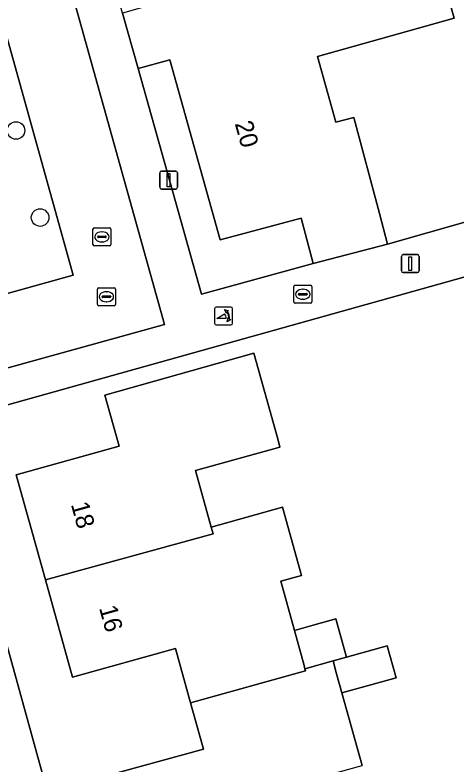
# Model space of a CAD drawing. Extents: x 159626 to 160723, y 388173 to 389416.
# Drawn here: x 159874.74 to 159899.35, y 388342.68 to 388384.45 of the extents above; entities that cross this region are included whole.
import ezdxf

# ---------------------------------------------------------------- set-up
doc = ezdxf.new("R2010")
doc.units = 0
for name, color, linetype in [('IMGEO_Boom', 7, 'Continuous'), ('IMGEO_Erf', 7, 'Continuous'), ('IMGEO_Kolk', 7, 'Continuous'), ('IMGEO_Lichtmast', 7, 'Continuous'), ('IMGEO_Muur', 7, 'Continuous'), ('IMGEO_Pand', 7, 'Continuous'), ('IMGEO_Pand_nummerreeks', 7, 'Continuous'), ('IMGEO_Poller', 7, 'Continuous'), ('IMGEO_Rijbaan_lokaal_open', 7, 'Continuous'), ('IMGEO_Rioolput', 7, 'Continuous'), ('IMGEO_Voetpad_open', 7, 'Continuous')]:
    doc.layers.add(name, color=color, linetype=linetype)

msp = doc.modelspace()

# ---------------------------------------------------------------- linework, layer by layer
at = {"layer": 'IMGEO_Boom'}
for centre in [(159874.792, 388378.012), (159876.137, 388373.166)]:
    msp.add_circle(centre, 0.489, dxfattribs=at)
at = {"layer": 'IMGEO_Erf'}
for points in [[(159897.841, 388389.08), (159899.191, 388384.265), (159891.585, 388382.133), (159892.611, 388378.475), (159893.612, 388378.74), (159895.026, 388373.388), (159895.473, 388371.693), (159906.895, 388374.924), (159927.612, 388380.783), (159924.091, 388393.285)], [(159928.443, 388377.878), (159922.592, 388376.25), (159923.589, 388372.697), (159917.967, 388371.119), (159916.97, 388374.672), (159872.396, 388362.2)], [(159879.487, 388341.978), (159885.23, 388343.569), (159884.516, 388346.144), (159883.678, 388349.167), (159877.935, 388347.575), (159876.429, 388352.983), (159874.798, 388358.84), (159880.533, 388360.43), (159879.743, 388363.284), (159888.04, 388365.621), (159889.386, 388360.769), (159889.493, 388360.383), (159884.791, 388359.08), (159885.664, 388355.932), (159889.63, 388357.031), (159890.683, 388353.233), (159889.532, 388352.914), (159890.293, 388350.17), (159891.347, 388350.462), (159892.607, 388350.811), (159893.195, 388348.685), (159895.465, 388349.314), (159895.961, 388347.528), (159892.943, 388346.691), (159894.061, 388342.653)], [(159871.278, 388360.217), (159878.48, 388334.175)]]:
    msp.add_lwpolyline(points, dxfattribs=at)
msp.add_lwpolyline([(159885.125, 388368.905), (159891.335, 388370.601), (159890.887, 388372.296), (159890.669, 388373.125), (159886.156, 388371.934), (159883.367, 388381.942), (159881.588, 388381.462)], close=True, dxfattribs=at)
at = {"layer": 'IMGEO_Kolk'}
for p, q in [((159879.08, 388371.665), (159879.08, 388372.517)), ((159879.155, 388372.591), (159880.007, 388372.591)), ((159880.081, 388372.517), (159880.081, 388371.665)), ((159879.339, 388372.085), (159879.339, 388372.097)), ((159879.777, 388372.048), (159879.379, 388372.048)), ((159879.382, 388372.134), (159879.78, 388372.134)), ((159879.568, 388372.371), (159879.593, 388372.371)), ((159879.823, 388372.097), (159879.823, 388372.085)), ((159879.591, 388371.811), (159879.566, 388371.811)), ((159880.007, 388371.591), (159879.155, 388371.591)), ((159890.264, 388368.468), (159890.264, 388369.32)), ((159890.339, 388369.394), (159891.191, 388369.394)), ((159890.752, 388369.174), (159890.777, 388369.174)), ((159891.265, 388369.32), (159891.265, 388368.468)), ((159890.523, 388368.888), (159890.523, 388368.9)), ((159890.961, 388368.851), (159890.563, 388368.851)), ((159890.566, 388368.937), (159890.964, 388368.937)), ((159891.007, 388368.9), (159891.007, 388368.888)), ((159891.191, 388368.394), (159890.339, 388368.394)), ((159890.775, 388368.614), (159890.75, 388368.614))]:
    msp.add_line(p, q, dxfattribs=at)
for points in [[(159879.08, 388371.665), (159879.08, 388372.517)], [(159879.155, 388372.591), (159880.007, 388372.591)], [(159880.081, 388372.517), (159880.081, 388371.665)], [(159880.007, 388371.591), (159879.155, 388371.591)], [(159890.264, 388368.468), (159890.264, 388369.32)], [(159890.339, 388369.394), (159891.191, 388369.394)], [(159891.265, 388369.32), (159891.265, 388368.468)], [(159891.191, 388368.394), (159890.339, 388368.394)]]:
    msp.add_lwpolyline(points, dxfattribs=at)
for centre, radius, start, end in [((159879.157, 388372.515), 0.0765, 91.552, 178.448), ((159879.157, 388372.515), 0.0765, 91.552, 178.448), ((159880.005, 388372.515), 0.0765, 1.552, 88.448), ((159880.005, 388372.515), 0.0765, 1.552, 88.448), ((159879.379, 388372.094), 0.0403, 85.8775, 175.7526), ((159879.376, 388372.084), 0.0366, 178.938, 274.7102), ((159879.78, 388372.091), 0.043, 264.8664, 352.4533), ((159879.784, 388372.096), 0.0386, 1.7309, 96.639), ((159879.157, 388371.667), 0.0765, 181.552, 268.448), ((159879.157, 388371.667), 0.0765, 181.552, 268.448), ((159880.005, 388371.667), 0.0765, 271.552, 358.448), ((159880.005, 388371.667), 0.0765, 271.552, 358.448), ((159890.341, 388369.318), 0.0765, 91.552, 178.448), ((159890.341, 388369.318), 0.0765, 91.552, 178.448), ((159891.189, 388369.318), 0.0765, 1.552, 88.448), ((159891.189, 388369.318), 0.0765, 1.552, 88.448), ((159890.563, 388368.897), 0.0403, 85.8775, 175.7526), ((159890.56, 388368.887), 0.0366, 178.938, 274.7102), ((159890.964, 388368.894), 0.043, 264.8664, 352.4533), ((159890.968, 388368.899), 0.0386, 1.7309, 96.639), ((159890.341, 388368.47), 0.0765, 181.552, 268.448), ((159890.341, 388368.47), 0.0765, 181.552, 268.448), ((159891.189, 388368.47), 0.0765, 271.552, 358.448), ((159891.189, 388368.47), 0.0765, 271.552, 358.448)]:
    msp.add_arc(centre, radius, start, end, dxfattribs=at)
for centre, major_axis, ratio, start_param, end_param in [((159879.567, 388372.091), (-0.387, 0.002), 0.722429, 4.712389, 7.853982), ((159879.592, 388372.091), (-0.39, 0.002), 0.717154, 1.570796, 4.712389), ((159890.751, 388368.894), (-0.387, 0.002), 0.722429, 4.712389, 7.853982), ((159890.776, 388368.894), (-0.39, 0.002), 0.717154, 1.570796, 4.712389)]:
    msp.add_ellipse(centre, major_axis=major_axis, ratio=ratio, start_param=start_param, end_param=end_param, dxfattribs=at)
at = {"layer": 'IMGEO_Lichtmast'}
for p, q in [((159882.795, 388374.852), (159882.795, 388375.652)), ((159882.795, 388375.652), (159882.795, 388374.852)), ((159882.895, 388375.752), (159883.685, 388375.752)), ((159883.685, 388375.752), (159882.895, 388375.752)), ((159883.785, 388375.652), (159883.785, 388374.852)), ((159883.785, 388374.852), (159883.785, 388375.652)), ((159883.685, 388374.752), (159882.895, 388374.752)), ((159882.895, 388374.752), (159883.685, 388374.752)), ((159896.252, 388370.201), (159896.252, 388371.001)), ((159896.252, 388371.001), (159896.252, 388370.201)), ((159896.352, 388371.101), (159897.142, 388371.101)), ((159897.142, 388371.101), (159896.352, 388371.101)), ((159897.242, 388371.001), (159897.242, 388370.201)), ((159897.242, 388370.201), (159897.242, 388371.001)), ((159897.142, 388370.101), (159896.352, 388370.101)), ((159896.352, 388370.101), (159897.142, 388370.101))]:
    msp.add_line(p, q, dxfattribs=at)
for points in [[(159883.215, 388375.627), (159883.365, 388375.627), (159883.365, 388374.877), (159883.215, 388374.877), (159883.215, 388375.627)], [(159896.672, 388370.976), (159896.822, 388370.976), (159896.822, 388370.226), (159896.672, 388370.226), (159896.672, 388370.976)]]:
    msp.add_lwpolyline(points, dxfattribs=at)
for centre, start, end in [((159882.895, 388375.652), 90, 180), ((159882.895, 388375.652), 90, 180), ((159883.685, 388375.652), 0, 90), ((159883.685, 388375.652), 360, 90), ((159882.895, 388374.852), 180, 270), ((159882.895, 388374.852), 180, 270), ((159883.685, 388374.852), 270, 0), ((159883.685, 388374.852), 270, 0), ((159896.352, 388371.001), 90, 180), ((159896.352, 388371.001), 90, 180), ((159897.142, 388371.001), 0, 90), ((159897.142, 388371.001), 360, 90), ((159896.352, 388370.201), 180, 270), ((159896.352, 388370.201), 180, 270), ((159897.142, 388370.201), 270, 0), ((159897.142, 388370.201), 270, 0)]:
    msp.add_arc(centre, 0.1, start, end, dxfattribs=at)
at = {"layer": 'IMGEO_Muur'}
msp.add_lwpolyline([(159895.473, 388371.693), (159906.895, 388374.924)], dxfattribs=at)
at = {"layer": 'IMGEO_Pand'}
for points in [[(159897.753, 388389.394), (159880.723, 388384.547), (159881.588, 388381.462), (159883.367, 388381.942), (159886.156, 388371.934), (159890.669, 388373.125), (159890.887, 388372.296), (159891.335, 388370.601), (159895.473, 388371.693), (159895.026, 388373.388), (159893.612, 388378.74), (159892.611, 388378.475), (159891.585, 388382.133), (159899.191, 388384.265), (159897.841, 388389.08)], [(159889.493, 388360.383), (159889.386, 388360.769), (159888.04, 388365.621), (159879.743, 388363.284), (159880.533, 388360.43), (159874.798, 388358.84), (159876.429, 388352.983), (159885.769, 388355.555), (159885.664, 388355.932), (159884.791, 388359.08)], [(159885.664, 388355.932), (159885.769, 388355.555), (159876.429, 388352.983), (159877.935, 388347.575), (159883.678, 388349.167), (159884.516, 388346.144), (159890.918, 388347.916), (159890.882, 388348.044), (159890.832, 388348.226), (159890.293, 388350.17), (159889.532, 388352.914), (159890.683, 388353.233), (159889.63, 388357.031)], [(159890.293, 388350.17), (159890.832, 388348.226), (159890.882, 388348.044), (159892.448, 388348.478), (159893.195, 388348.685), (159892.607, 388350.811), (159891.347, 388350.462)], [(159895.465, 388349.314), (159893.195, 388348.685), (159892.448, 388348.478), (159892.646, 388347.764), (159892.943, 388346.691), (159895.961, 388347.528)], [(159894.061, 388342.653), (159892.943, 388346.691), (159892.646, 388347.764), (159892.448, 388348.478), (159890.882, 388348.044), (159890.918, 388347.916), (159884.516, 388346.144), (159885.23, 388343.569), (159879.487, 388341.978), (159881.098, 388336.221), (159883.364, 388336.844), (159883.902, 388334.886), (159888.714, 388336.209), (159888.176, 388338.166), (159890.43, 388338.786), (159889.693, 388341.442)]]:
    msp.add_lwpolyline(points, close=True, dxfattribs=at)
at = {"layer": 'IMGEO_Poller'}
for p, q in [((159885.853, 388368.087), (159885.853, 388367.28)), ((159885.853, 388368.087), (159885.853, 388367.28)), ((159886.755, 388368.182), (159885.947, 388368.182)), ((159886.755, 388368.182), (159885.947, 388368.182)), ((159886.849, 388367.28), (159886.849, 388368.087)), ((159886.849, 388367.28), (159886.849, 388368.087)), ((159885.947, 388367.185), (159886.755, 388367.185)), ((159885.947, 388367.185), (159886.755, 388367.185))]:
    msp.add_line(p, q, dxfattribs=at)
for points in [[(159886.532, 388367.911), (159886.52, 388367.838), (159886.395, 388368.043)], [(159886.395, 388368.043), (159886.626, 388367.977), (159886.555, 388367.945)], [(159886.488, 388367.538), (159885.975, 388367.538), (159886.405, 388367.813)], [(159886.548, 388367.366), (159886.614, 388367.597), (159886.644, 388367.529)], [(159886.68, 388367.502), (159886.752, 388367.491), (159886.548, 388367.366)]]:
    msp.add_lwpolyline(points, dxfattribs=at)
for centre, radius, start, end in [((159885.947, 388368.087), 0.0946, 90, 180), ((159885.947, 388368.087), 0.0946, 90, 180), ((159886.174, 388367.598), 0.476, 351.7527, 41.1691), ((159886.174, 388367.598), 0.516, 349.3569, 42.2912), ((159886.755, 388368.087), 0.0946, 0, 90), ((159886.755, 388368.087), 0.0946, 0, 90), ((159886.16, 388367.588), 0.332, 351.3247, 42.4854), ((159885.947, 388367.28), 0.0946, 180, 270), ((159885.947, 388367.28), 0.0946, 180, 270), ((159886.755, 388367.28), 0.0946, 270, 0), ((159886.755, 388367.28), 0.0946, 270, 0)]:
    msp.add_arc(centre, radius, start, end, dxfattribs=at)
at = {"layer": 'IMGEO_Rijbaan_lokaal_open'}
msp.add_lwpolyline([(159886.13, 388299.399), (159880.05, 388321.131), (159878.62, 388326.151), (159877.583, 388329.947), (159868.371, 388363.142), (159883.064, 388367.211), (159871.974, 388406.867), (159868.033, 388405.666), (159877.981, 388369.955), (159863.419, 388365.912), (159864.8, 388360.991), (159882.996, 388295.92)], dxfattribs=at)
at = {"layer": 'IMGEO_Rioolput'}
for p, q in [((159879.329, 388368.332), (159879.329, 388369.184)), ((159879.404, 388369.258), (159880.256, 388369.258)), ((159880.33, 388369.184), (159880.33, 388368.332)), ((159879.588, 388368.752), (159879.588, 388368.764)), ((159880.026, 388368.715), (159879.628, 388368.715)), ((159879.631, 388368.801), (159880.029, 388368.801)), ((159879.817, 388369.038), (159879.842, 388369.038)), ((159880.072, 388368.764), (159880.072, 388368.752)), ((159880.256, 388368.258), (159879.404, 388368.258)), ((159879.84, 388368.478), (159879.815, 388368.478))]:
    msp.add_line(p, q, dxfattribs=at)
for points in [[(159879.329, 388368.332), (159879.329, 388369.184)], [(159879.404, 388369.258), (159880.256, 388369.258)], [(159880.33, 388369.184), (159880.33, 388368.332)], [(159880.256, 388368.258), (159879.404, 388368.258)]]:
    msp.add_lwpolyline(points, dxfattribs=at)
for centre, radius, start, end in [((159879.406, 388369.182), 0.0765, 91.552, 178.448), ((159879.406, 388369.182), 0.0765, 91.552, 178.448), ((159880.254, 388369.182), 0.0765, 1.552, 88.448), ((159880.254, 388369.182), 0.0765, 1.552, 88.448), ((159879.628, 388368.761), 0.0403, 85.8775, 175.7526), ((159879.625, 388368.751), 0.0366, 178.938, 274.7102), ((159880.029, 388368.758), 0.043, 264.8664, 352.4533), ((159880.033, 388368.763), 0.0386, 1.7309, 96.639), ((159879.406, 388368.334), 0.0765, 181.552, 268.448), ((159879.406, 388368.334), 0.0765, 181.552, 268.448), ((159880.254, 388368.334), 0.0765, 271.552, 358.448), ((159880.254, 388368.334), 0.0765, 271.552, 358.448)]:
    msp.add_arc(centre, radius, start, end, dxfattribs=at)
for centre, major_axis, ratio, start_param, end_param in [((159879.816, 388368.758), (-0.387, 0.002), 0.722429, 4.712389, 7.853982), ((159879.841, 388368.758), (-0.39, 0.002), 0.717154, 1.570796, 4.712389)]:
    msp.add_ellipse(centre, major_axis=major_axis, ratio=ratio, start_param=start_param, end_param=end_param, dxfattribs=at)
at = {"layer": 'IMGEO_Voetpad_open'}
for points in [[(159890.763, 388466.088), (159889.278, 388465.962), (159890.351, 388462.109), (159858.976, 388453.345), (159871.183, 388409.697), (159871.974, 388406.867), (159883.064, 388367.211), (159868.371, 388363.142), (159877.583, 388329.947), (159898.714, 388335.876), (159901.439, 388336.64), (159939.056, 388347.194), (159938.495, 388349.196), (159935.001, 388348.184)], [(159872.396, 388362.2), (159916.97, 388374.672), (159922.592, 388376.25), (159928.443, 388377.878), (159927.612, 388380.783), (159906.895, 388374.924), (159895.473, 388371.693), (159891.335, 388370.601), (159885.125, 388368.905), (159881.588, 388381.462), (159880.723, 388384.547), (159879.649, 388388.378), (159872.648, 388413.43), (159871.81, 388416.443), (159870.719, 388420.363), (159863.708, 388445.396), (159862.717, 388449.025), (159862.457, 388449.987)], [(159877.981, 388369.955), (159868.033, 388405.666)], [(159873.074, 388370.622), (159860.895, 388367.226), (159861.364, 388365.632), (159861.887, 388364.092), (159862.302, 388362.646), (159862.784, 388360.92), (159881.089, 388295.408), (159882.996, 388295.92), (159864.8, 388360.991), (159863.419, 388365.912), (159877.981, 388369.955)], [(159878.48, 388334.175), (159871.278, 388360.217)]]:
    msp.add_lwpolyline(points, dxfattribs=at)

# ---------------------------------------------------------------- texts
at = {"layer": 'IMGEO_Pand_nummerreeks'}
for s, rotation, p in [('20', 285.5719, (159886.968, 388378.407)), ('18', 285.5613, (159877.844, 388357.197)), ('16', 285.5613, (159879.412, 388351.43))]:
    msp.add_text(s, height=1, rotation=rotation, dxfattribs=at).set_placement(p)

doc.saveas('drawing.dxf')
